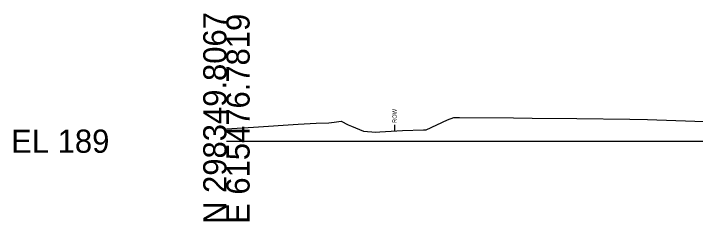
# Model space of a CAD drawing. Extents: x 517327 to 517505, y 114839 to 116885.
# Drawn here: x 517326.7 to 517409, y 115338.7 to 115363.8 of the extents above; entities that cross this region are included whole.
import ezdxf

# ---------------------------------------------------------------- set-up
doc = ezdxf.new("R2010")
doc.units = 0
for name, color, linetype in [('Exist XS Ground Line', 7, 'Continuous'), ('Old_Level_63', 7, 'Continuous'), ('Prop XS Exc Vertical Line 2', 7, 'Continuous')]:
    doc.layers.add(name, color=color, linetype=linetype)

msp = doc.modelspace()

# ---------------------------------------------------------------- linework, layer by layer
at = {"layer": 'Exist XS Ground Line'}
for p, q in [((517376.49, 115349.736), (517379.068, 115350.928)), ((517379.068, 115350.928), (517379.815, 115351.222)), ((517379.815, 115351.222), (517380.505, 115351.22)), ((517380.505, 115351.22), (517387.012, 115351.197)), ((517387.012, 115351.197), (517389.282, 115351.153)), ((517389.282, 115351.153), (517394.652, 115351.089)), ((517394.652, 115351.089), (517401.081, 115351.039)), ((517401.081, 115351.039), (517403.207, 115350.994)), ((517403.207, 115350.994), (517408.936, 115350.767)), ((517352.365, 115349.852), (517355.648, 115350.059)), ((517355.648, 115350.059), (517361.035, 115350.417)), ((517361.035, 115350.417), (517363.193, 115350.532)), ((517363.193, 115350.532), (517364.747, 115350.596)), ((517364.747, 115350.596), (517365.385, 115350.68)), ((517365.385, 115350.68), (517366.199, 115350.776)), ((517366.199, 115350.776), (517367.06, 115350.351)), ((517367.06, 115350.351), (517367.462, 115350.181)), ((517367.462, 115350.181), (517368.927, 115349.56)), ((517408.936, 115350.767), (517412.177, 115350.652)), ((517368.927, 115349.56), (517370.415, 115349.47)), ((517370.415, 115349.47), (517370.886, 115349.492)), ((517370.886, 115349.492), (517373.628, 115349.66)), ((517373.628, 115349.66), (517376.157, 115349.735)), ((517376.157, 115349.735), (517376.49, 115349.736))]:
    msp.add_line(p, q, dxfattribs=at)
at = {"layer": 'Old_Level_63'}
msp.add_line((517352.365, 115348.365), (517427.365, 115348.365), dxfattribs=at)
at = {"layer": 'Prop XS Exc Vertical Line 2'}
msp.add_line((517372.663, 115350.351), (517372.663, 115349.601), dxfattribs=at)

# ---------------------------------------------------------------- texts
at = {"layer": 'Old_Level_63'}
for s, p in [('N 298349.8067', (517352.365, 115338.364)), ('E 615476.7819', (517355.165, 115338.365))]:
    msp.add_text(s, height=2.8, rotation=90, dxfattribs=at).set_placement(p)
msp.add_text('EL 189', height=2.8, dxfattribs=at).set_placement((517326.366, 115346.965))
at = {"layer": 'Prop XS Exc Vertical Line 2'}
msp.add_text('ROW', height=0.5, rotation=90, dxfattribs=at).set_placement((517372.913, 115350.576))

doc.saveas('drawing.dxf')
